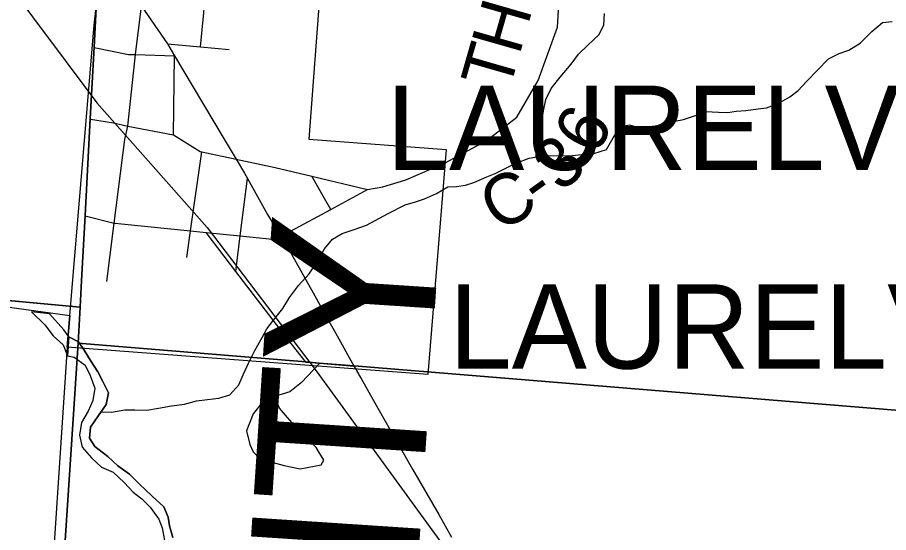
# Model space of a CAD drawing. Extents: x 0 to 42.5, y 0 to 22.
# Drawn here: x 8.1346 to 8.6245, y 15.4887 to 15.7782 of the extents above; entities that cross this region are included whole.
import ezdxf

# ---------------------------------------------------------------- set-up
doc = ezdxf.new("R2010")
doc.units = 0
for name, color, linetype in [('GM_X_City_Street', 7, 'Continuous'), ('GM_X_Corporation', 7, 'Continuous'), ('GM_X_Corporation_Text', 7, 'Continuous'), ('GM_X_County_Road', 7, 'Continuous'), ('GM_X_County_Road_Text', 7, 'Continuous'), ('GM_X_County_Text', 7, 'Continuous'), ('GM_X_Interchange_Ramps', 7, 'Continuous'), ('GM_X_Major_River', 7, 'Continuous'), ('GM_X_Minor_Lake', 7, 'Continuous'), ('GM_X_Minor_River', 7, 'Continuous'), ('GM_X_Rail_Line', 7, 'Continuous'), ('GM_X_State_Route', 7, 'Continuous'), ('GM_X_Township', 7, 'Continuous'), ('GM_X_Township_Road', 7, 'Continuous'), ('SH_Cut_Line', 7, 'Continuous')]:
    doc.layers.add(name, color=color, linetype=linetype)

msp = doc.modelspace()

# ---------------------------------------------------------------- linework, layer by layer
at = {"layer": 'GM_X_City_Street'}
for p, q in [((8.22234, 15.71215), (8.22295, 15.75664)), ((8.23197, 15.65827), (8.23831, 15.70274)), ((8.30735, 15.67655), (8.30026, 15.68894)), ((8.31089, 15.67036), (8.30735, 15.67655)), ((8.22983, 15.64328), (8.23197, 15.65827)), ((8.28649, 15.59759), (8.30983, 15.60755))]:
    msp.add_line(p, q, dxfattribs=at)
for points in [[(8.23767, 15.76161), (8.23941, 15.78086), (8.23963, 15.78334), (8.24416, 15.83383), (8.24464, 15.83913), (8.25024, 15.88911), (8.25294, 15.9159), (8.25382, 15.9273), (8.24973, 15.9332)], [(8.19499, 15.70965), (8.19673, 15.71712), (8.20101, 15.75731), (8.20445, 15.78454)], [(8.21898, 15.76345), (8.23767, 15.76161), (8.25365, 15.76011)], [(8.17086, 15.63018), (8.17281, 15.66664), (8.17572, 15.72112), (8.17786, 15.76131)], [(8.17786, 15.76131), (8.19717, 15.75743), (8.19765, 15.75742)], [(8.19765, 15.75742), (8.20101, 15.75731), (8.22295, 15.75664)], [(8.17572, 15.72112), (8.1886, 15.71895), (8.19673, 15.71712), (8.22234, 15.71215), (8.23744, 15.70293), (8.23831, 15.70274), (8.25756, 15.6986), (8.27949, 15.69389), (8.30026, 15.68894), (8.33144, 15.68151)], [(8.1849, 15.62977), (8.18905, 15.66262), (8.19499, 15.70965)], [(8.19322, 15.66218), (8.23197, 15.65827), (8.24084, 15.65737), (8.25998, 15.65544), (8.27972, 15.65345), (8.28278, 15.65511), (8.28857, 15.65825), (8.31089, 15.67036), (8.33144, 15.68151), (8.34017, 15.68308), (8.35307, 15.68696), (8.37508, 15.69643)], [(8.25754, 15.63551), (8.25998, 15.65544), (8.26395, 15.68776)], [(8.17281, 15.66664), (8.18905, 15.66262), (8.1896, 15.66255), (8.19322, 15.66218)], [(8.32405, 15.58212), (8.30443, 15.58373), (8.29698, 15.58434), (8.28649, 15.59759), (8.25754, 15.63551), (8.24084, 15.65737)]]:
    msp.add_lwpolyline(points, dxfattribs=at)
at = {"layer": 'GM_X_Corporation'}
msp.add_lwpolyline([(8.3164, 15.94888), (8.29852, 15.70973), (8.37568, 15.70396), (8.36548, 15.57764), (8.16271, 15.59296), (8.16418, 15.61064), (8.17779, 15.77395), (8.18543, 15.84177)], dxfattribs=at)
msp.add_lwpolyline([(7.91921, 15.63683), (7.95331, 15.6361), (7.97957, 15.63417), (8.04805, 15.62672), (8.16418, 15.61064), (8.16271, 15.59296), (8.14602, 15.34154), (7.89922, 15.35961), (7.91813, 15.60669)], close=True, dxfattribs=at)
at = {"layer": 'GM_X_County_Road'}
msp.add_lwpolyline([(8.37508, 15.69643), (8.39816, 15.70896), (8.41554, 15.7222), (8.42736, 15.7428), (8.43835, 15.7727), (8.4397, 15.7955), (8.44667, 15.82993), (8.44993, 15.85218), (8.44881, 15.87648), (8.45084, 15.91049), (8.45452, 15.92704), (8.46847, 15.94215), (8.51672, 15.96646), (8.5443, 15.98738), (8.56907, 16.00181), (8.59144, 16.00749), (8.59942, 16.00794), (8.62254, 16.01401)], dxfattribs=at)
at = {"layer": 'GM_X_Interchange_Ramps'}
for points in [[(8.24781, 16.59008), (8.17933, 15.79111), (8.17776, 15.76158), (8.17561, 15.72139), (8.1727, 15.66691), (8.17075, 15.63044), (8.16995, 15.61544), (8.16884, 15.59509), (8.29687, 15.58461), (8.30432, 15.58399), (8.32394, 15.58239), (8.67633, 15.55354), (8.9, 15.53758), (8.9, 19.05381)], [(5.08492, 14.1), (8.06989, 14.1), (8.07009, 14.10263), (8.07289, 14.12804), (8.09551, 14.48695), (8.1568, 15.41315), (8.16884, 15.59509), (8.16995, 15.61544), (8.04805, 15.62672), (7.97957, 15.63417), (7.95331, 15.6361), (7.91921, 15.63683), (7.91813, 15.60669), (7.88151, 15.60844), (7.87674, 15.60879), (7.42273, 15.64192), (7.26665, 15.65331), (5.92916, 15.74982)]]:
    msp.add_lwpolyline(points, dxfattribs=at)
msp.add_lwpolyline([(8.06989, 14.1), (8.9, 14.1), (8.9, 15.53758), (8.67633, 15.55354), (8.32394, 15.58239), (8.30432, 15.58399), (8.29687, 15.58461), (8.16884, 15.59509), (8.1568, 15.41315), (8.09551, 14.48695), (8.07289, 14.12804), (8.07009, 14.10263)], close=True, dxfattribs=at)
at = {"layer": 'GM_X_Major_River'}
for p, q in [((8.16356, 15.59873), (8.16285, 15.58805)), ((8.16897, 15.59594), (8.16356, 15.59873)), ((8.17215, 15.59118), (8.16897, 15.59594)), ((8.17571, 15.58546), (8.17215, 15.59118)), ((8.16285, 15.58805), (8.16663, 15.58723)), ((8.16663, 15.58723), (8.17266, 15.58283)), ((8.17266, 15.58283), (8.17564, 15.57693)), ((8.17982, 15.57899), (8.17571, 15.58546)), ((8.17564, 15.57693), (8.17824, 15.5699)), ((8.18263, 15.57366), (8.17982, 15.57899)), ((8.1858, 15.56719), (8.18263, 15.57366)), ((8.17824, 15.5699), (8.17706, 15.56289)), ((8.18462, 15.56075), (8.1858, 15.56719)), ((8.17706, 15.56289), (8.17436, 15.55703)), ((8.17436, 15.55703), (8.17072, 15.5506)), ((8.18022, 15.55452), (8.18462, 15.56075)), ((8.17581, 15.54792), (8.18022, 15.55452)), ((8.17072, 15.5506), (8.16953, 15.54341)), ((8.1752, 15.54185), (8.17581, 15.54792)), ((8.16953, 15.54341), (8.171, 15.53676)), ((8.1782, 15.53709), (8.1752, 15.54185)), ((8.171, 15.53676), (8.17626, 15.53066)), ((8.18554, 15.53154), (8.1782, 15.53709)), ((8.17626, 15.53066), (8.1819, 15.5255)), ((8.19118, 15.5262), (8.18554, 15.53154)), ((8.1819, 15.5255), (8.1885, 15.52261)), ((8.1885, 15.52261), (8.19471, 15.51688)), ((8.19759, 15.5216), (8.19118, 15.5262)), ((8.20304, 15.51607), (8.19759, 15.5216)), ((8.19471, 15.51688), (8.19979, 15.51154)), ((8.21037, 15.50919), (8.20304, 15.51607)), ((8.19979, 15.51154), (8.20468, 15.50771)), ((8.21696, 15.50327), (8.21037, 15.50919)), ((8.20468, 15.50771), (8.20938, 15.50294)), ((8.21937, 15.49738), (8.21696, 15.50327)), ((8.20938, 15.50294), (8.21425, 15.49627)), ((8.21425, 15.49627), (8.21611, 15.49133)), ((8.2201, 15.49244), (8.21937, 15.49738)), ((8.21611, 15.49133), (8.21739, 15.4843)), ((8.22194, 15.48598), (8.2201, 15.49244))]:
    msp.add_line(p, q, dxfattribs=at)
for points in [[(8.16356, 15.59873), (8.16897, 15.59594), (8.17215, 15.59118), (8.17571, 15.58546), (8.17982, 15.57899), (8.18263, 15.57366), (8.1858, 15.56719), (8.18462, 15.56075), (8.18022, 15.55452), (8.17581, 15.54792), (8.1752, 15.54185), (8.1782, 15.53709), (8.18554, 15.53154), (8.19118, 15.5262), (8.19759, 15.5216), (8.20304, 15.51607), (8.21037, 15.50919), (8.21696, 15.50327), (8.21937, 15.49738), (8.2201, 15.49244), (8.22194, 15.48598)], [(8.16285, 15.58805), (8.16663, 15.58723), (8.17266, 15.58283), (8.17564, 15.57693), (8.17824, 15.5699), (8.17706, 15.56289), (8.17436, 15.55703), (8.17072, 15.5506), (8.16953, 15.54341), (8.171, 15.53676), (8.17626, 15.53066), (8.1819, 15.5255), (8.1885, 15.52261), (8.19471, 15.51688), (8.19979, 15.51154), (8.20468, 15.50771), (8.20938, 15.50294), (8.21425, 15.49627), (8.21611, 15.49133), (8.21739, 15.4843)]]:
    msp.add_lwpolyline(points, dxfattribs=at)
at = {"layer": 'GM_X_Minor_Lake'}
for p, q in [((8.15269, 15.61167), (8.1425, 15.61269)), ((8.16285, 15.58805), (8.16356, 15.59873))]:
    msp.add_line(p, q, dxfattribs=at)
for points in [[(8.1425, 15.61269), (8.15, 15.60552), (8.15475, 15.59927), (8.16044, 15.59417), (8.16285, 15.58805)], [(8.16356, 15.59873), (8.1608, 15.60271), (8.15269, 15.61167)]]:
    msp.add_lwpolyline(points, dxfattribs=at)
at = {"layer": 'GM_X_Minor_River'}
for p, q in [((8.46431, 15.77381), (8.46474, 15.78044)), ((8.46162, 15.76851), (8.46431, 15.77381)), ((8.61501, 15.77036), (8.6211, 15.77544)), ((8.6211, 15.77544), (8.62641, 15.77598)), ((8.45533, 15.76268), (8.46162, 15.76851)), ((8.60852, 15.76377), (8.61501, 15.77036)), ((8.45018, 15.75759), (8.45533, 15.76268)), ((8.60205, 15.75983), (8.60852, 15.76377)), ((8.59066, 15.75497), (8.59674, 15.75797)), ((8.59674, 15.75797), (8.60205, 15.75983)), ((8.44598, 15.75193), (8.45018, 15.75759)), ((8.58455, 15.74856), (8.59066, 15.75497)), ((8.43986, 15.74457), (8.44598, 15.75193)), ((8.57826, 15.74216), (8.58455, 15.74856)), ((8.4347, 15.73834), (8.43986, 15.74457)), ((8.43182, 15.7321), (8.4347, 15.73834)), ((8.57368, 15.73707), (8.57826, 15.74216)), ((8.56245, 15.72993), (8.56892, 15.73368)), ((8.56892, 15.73368), (8.57368, 15.73707)), ((8.43064, 15.72661), (8.43182, 15.7321)), ((8.55581, 15.72732), (8.56245, 15.72993)), ((8.42946, 15.71998), (8.43064, 15.72661)), ((8.51582, 15.72303), (8.52171, 15.72526)), ((8.52171, 15.72526), (8.5289, 15.72503)), ((8.5289, 15.72503), (8.53401, 15.72481)), ((8.53401, 15.72481), (8.53875, 15.72553)), ((8.53875, 15.72553), (8.54425, 15.72588)), ((8.54425, 15.72588), (8.55107, 15.72678)), ((8.55107, 15.72678), (8.55581, 15.72732)), ((8.42865, 15.71259), (8.42946, 15.71998)), ((8.49685, 15.71765), (8.50425, 15.71988)), ((8.50425, 15.71988), (8.50918, 15.7208)), ((8.50918, 15.7208), (8.51582, 15.72303)), ((8.46953, 15.71062), (8.47393, 15.71685)), ((8.47393, 15.71685), (8.47886, 15.71777)), ((8.47886, 15.71777), (8.48434, 15.71621)), ((8.48434, 15.71621), (8.49135, 15.71655)), ((8.49135, 15.71655), (8.49685, 15.71765)), ((8.42765, 15.70558), (8.42865, 15.71259)), ((8.46589, 15.70401), (8.46953, 15.71062)), ((8.42752, 15.70006), (8.42765, 15.70558)), ((8.45868, 15.70178), (8.46589, 15.70401)), ((8.41547, 15.69656), (8.4223, 15.69917)), ((8.4223, 15.69917), (8.42875, 15.70027)), ((8.42875, 15.70027), (8.43348, 15.70061)), ((8.43348, 15.70061), (8.44011, 15.70038)), ((8.44011, 15.70038), (8.44674, 15.70072)), ((8.44674, 15.70072), (8.45356, 15.70143)), ((8.45356, 15.70143), (8.45868, 15.70178)), ((8.40996, 15.69394), (8.41547, 15.69656)), ((8.39856, 15.6887), (8.4033, 15.69057)), ((8.4033, 15.69057), (8.40996, 15.69394)), ((8.3866, 15.68404), (8.39134, 15.68553)), ((8.39134, 15.68553), (8.39856, 15.6887)), ((8.37028, 15.67921), (8.37674, 15.68297)), ((8.37674, 15.68297), (8.38148, 15.68312)), ((8.38148, 15.68312), (8.3866, 15.68404)), ((8.35262, 15.67288), (8.3585, 15.67455)), ((8.3585, 15.67455), (8.36363, 15.67622)), ((8.36363, 15.67622), (8.37028, 15.67921)), ((8.34312, 15.66801), (8.35262, 15.67288)), ((8.33095, 15.66145), (8.33818, 15.66539)), ((8.33818, 15.66539), (8.34312, 15.66801)), ((8.32393, 15.65903), (8.33095, 15.66145)), ((8.31177, 15.65361), (8.31729, 15.6568)), ((8.31729, 15.6568), (8.32393, 15.65903)), ((8.30738, 15.64814), (8.31177, 15.65361)), ((8.30316, 15.64096), (8.30738, 15.64814)), ((8.29876, 15.63416), (8.30316, 15.64096)), ((8.29265, 15.62757), (8.29876, 15.63416)), ((8.28768, 15.62077), (8.29265, 15.62757)), ((8.28385, 15.61473), (8.28768, 15.62077)), ((8.27869, 15.60812), (8.28385, 15.61473)), ((8.27486, 15.60322), (8.27869, 15.60812)), ((8.27218, 15.5983), (8.27486, 15.60322)), ((8.26815, 15.59112), (8.27218, 15.5983)), ((8.2645, 15.58394), (8.26815, 15.59112)), ((8.26161, 15.57732), (8.2645, 15.58394)), ((8.25911, 15.57184), (8.26161, 15.57732)), ((8.25415, 15.56618), (8.25911, 15.57184)), ((8.22855, 15.56085), (8.23537, 15.5627)), ((8.23537, 15.5627), (8.24144, 15.56361)), ((8.24144, 15.56361), (8.24788, 15.56433)), ((8.24788, 15.56433), (8.25415, 15.56618)), ((8.18761, 15.55637), (8.19501, 15.55765)), ((8.19501, 15.55765), (8.20069, 15.5578)), ((8.20069, 15.5578), (8.2075, 15.55757)), ((8.2075, 15.55757), (8.21395, 15.55867)), ((8.21395, 15.55867), (8.22134, 15.55995)), ((8.22134, 15.55995), (8.22855, 15.56085)), ((8.18172, 15.55665), (8.18761, 15.55637))]:
    msp.add_line(p, q, dxfattribs=at)
at = {"layer": 'GM_X_Rail_Line'}
for points in [[(7.98347, 16.32444), (7.94829, 15.9349), (7.95454, 15.91522), (7.97421, 15.89822), (8.00014, 15.88211), (8.09048, 15.83928), (8.11148, 15.82198), (8.12531, 15.80248), (8.17938, 15.73019)], [(8.17938, 15.73019), (8.24138, 15.6602), (8.30262, 15.57959), (8.42318, 15.41403), (8.46804, 15.38328), (8.66065, 15.25025), (8.9, 15.08301)]]:
    msp.add_lwpolyline(points, dxfattribs=at)
at = {"layer": 'GM_X_State_Route'}
for points in [[(8.20445, 15.78454), (8.21898, 15.76345), (8.22295, 15.75664), (8.23879, 15.7302), (8.25091, 15.7098), (8.25756, 15.6986), (8.26225, 15.69072)], [(8.26225, 15.69072), (8.26303, 15.68941), (8.26395, 15.68776), (8.27533, 15.66749), (8.28278, 15.65511), (8.28876, 15.64519), (8.30086, 15.62347), (8.30983, 15.60755), (8.31353, 15.60098), (8.32405, 15.58212), (8.32642, 15.57787), (8.32666, 15.57743)], [(8.32666, 15.57743), (8.32788, 15.57525), (8.33658, 15.56004)], [(8.33658, 15.56004), (8.34204, 15.55048), (8.35676, 15.52437), (8.37168, 15.49883), (8.37878, 15.48616)]]:
    msp.add_lwpolyline(points, dxfattribs=at)
at = {"layer": 'GM_X_Township'}
msp.add_lwpolyline([(8.24781, 16.59008), (8.17933, 15.79111), (8.17776, 15.76158), (8.17561, 15.72139), (8.1727, 15.66691), (8.17075, 15.63044), (8.16995, 15.61544), (8.04805, 15.62672), (7.97957, 15.63417), (7.95331, 15.6361), (7.91921, 15.63683), (7.91813, 15.60669), (7.88151, 15.60844), (7.87674, 15.60879), (7.42273, 15.64192), (7.26665, 15.65331), (5.92916, 15.74982), (5.21422, 15.79865), (5.23885, 16.11392)], dxfattribs=at)
at = {"layer": 'GM_X_Township_Road'}
for points in [[(8.30443, 15.58373), (8.2943, 15.57312), (8.28788, 15.56775), (8.27916, 15.56513), (8.27879, 15.56503), (8.27235, 15.56175), (8.26727, 15.55544), (8.26354, 15.54592), (8.2653, 15.53815), (8.26723, 15.53418), (8.27087, 15.53022), (8.28457, 15.52652), (8.2937, 15.5245), (8.30546, 15.52687)], [(8.30546, 15.52687), (8.30696, 15.52935), (8.30254, 15.53653), (8.2924, 15.54671), (8.28206, 15.55859), (8.27916, 15.56513)]]:
    msp.add_lwpolyline(points, dxfattribs=at)
at = {"layer": 'SH_Cut_Line'}
for points in [[(8.24781, 16.59008), (8.17933, 15.79111), (8.17776, 15.76158), (8.17561, 15.72139), (8.1727, 15.66691), (8.17075, 15.63044), (8.16995, 15.61544), (8.16884, 15.59509), (8.1568, 15.41315), (8.09551, 14.48695), (8.07289, 14.12804), (8.07009, 14.10263), (8.06989, 14.1), (8.9, 14.1), (8.9, 19.05381)], [(3.72132, 15.90374), (4.44374, 15.85348), (4.57597, 15.84389), (4.70326, 15.83465), (4.83401, 15.82463), (5.0466, 15.8101), (5.21422, 15.79865), (5.92916, 15.74982), (7.26665, 15.65331), (7.42273, 15.64192), (7.87674, 15.60879), (7.88151, 15.60844), (7.91813, 15.60669), (7.91921, 15.63683), (7.95331, 15.6361), (7.97957, 15.63417), (8.04805, 15.62672), (8.16995, 15.61544), (8.17075, 15.63044), (8.1727, 15.66691), (8.17561, 15.72139), (8.17776, 15.76158), (8.17933, 15.79111), (8.24781, 16.59008)], [(2.1, 14.1), (8.06989, 14.1), (8.07009, 14.10263), (8.07289, 14.12804), (8.09551, 14.48695), (8.1568, 15.41315), (8.16884, 15.59509), (8.16995, 15.61544), (8.04805, 15.62672), (7.97957, 15.63417), (7.95331, 15.6361), (7.91921, 15.63683), (7.91813, 15.60669), (7.88151, 15.60844), (7.87674, 15.60879), (7.42273, 15.64192), (7.26665, 15.65331), (5.92916, 15.74982)]]:
    msp.add_lwpolyline(points, dxfattribs=at)

# ---------------------------------------------------------------- texts
at = {"layer": 'GM_X_Corporation_Text'}
for p in [(8.34215, 15.69254), (8.37738, 15.58087)]:
    msp.add_text('LAURELVILLE', height=0.0473485, rotation=0, dxfattribs=at).set_placement(p)
at = {"layer": 'GM_X_County_Road_Text'}
for s, rotation, p in [('H', 74.0476, (8.41685, 15.75642)), ('T', 74.0052, (8.41099, 15.73597)), ('6', 62.5986, (8.46019, 15.69979)), ('3', 42.0776, (8.44044, 15.67931)), ('C', 29.7294, (8.4053, 15.65702)), ('-', 35.7055, (8.42828, 15.67034))]:
    msp.add_text(s, height=0.02841, rotation=rotation, dxfattribs=at).set_placement(p)
at = {"layer": 'GM_X_County_Text'}
msp.add_text('HOCKING COUNTY', height=0.094697, rotation=86.2285, dxfattribs=at).set_placement((8.29618, 14.5044))

doc.saveas('drawing.dxf')
